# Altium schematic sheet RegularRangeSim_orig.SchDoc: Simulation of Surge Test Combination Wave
size B; SheetNumber: 1; PageSetup: Record=PageOptions¦CenterHorizontal=True¦CenterVertical=True¦PrintScale=0.72¦XCorrection=1.00¦YCorrection=1.00¦PrintKind=0¦BorderSize=5000000¦LeftOffset=0¦BottomOffset=0¦Orientation=2¦PaperLength=1000¦PaperWidth=1000¦Scale=100¦PaperSource=7¦PrintQuality=-4¦MediaType=1¦DitherType=10¦PrintScaleMode=1¦PaperKind=Letter¦PaperIndex=1; nhSheetName: Surge (Combo) Transient; SPICEModelCacheWJGPQAWH: <root> / <DocumentId>WJGPQAWH</DocumentId> / <CacheFrame Number="0"> / <Model Name="v20e275m" Kind="ckt"> / <Text>.subckt V20E275M 1 2 / R1 1 3 100u / B1 3 4 I=1.5e-12*(exp(abs(V(3,4))/22)-1)*sgn(V(3,4)) / C1 3 4 900pF / R2 3 4 4g / L1 4 2 12nH / .ends</Text> / </Model> / <Model Name="vlowr" Kind="mdl"> / <Text>.MODEL VLOWR VSWITCH(RON=1m ROFF=1MEG)</Text> / </Model> / <Model Name="v20e510m" Kind="ckt"> / <Text>.subckt V20E510M 1 2 / R1 1 3 100u / B1 3 4 I=1.0e-5*(exp(abs(V(3,4))/87)-1)*sgn(V(3,4)) / C1 3 4 350pF / R2 3 4 4g / L1 4 2 12nH / .ends</Text> / </Model> / </CacheFrame> / </root>
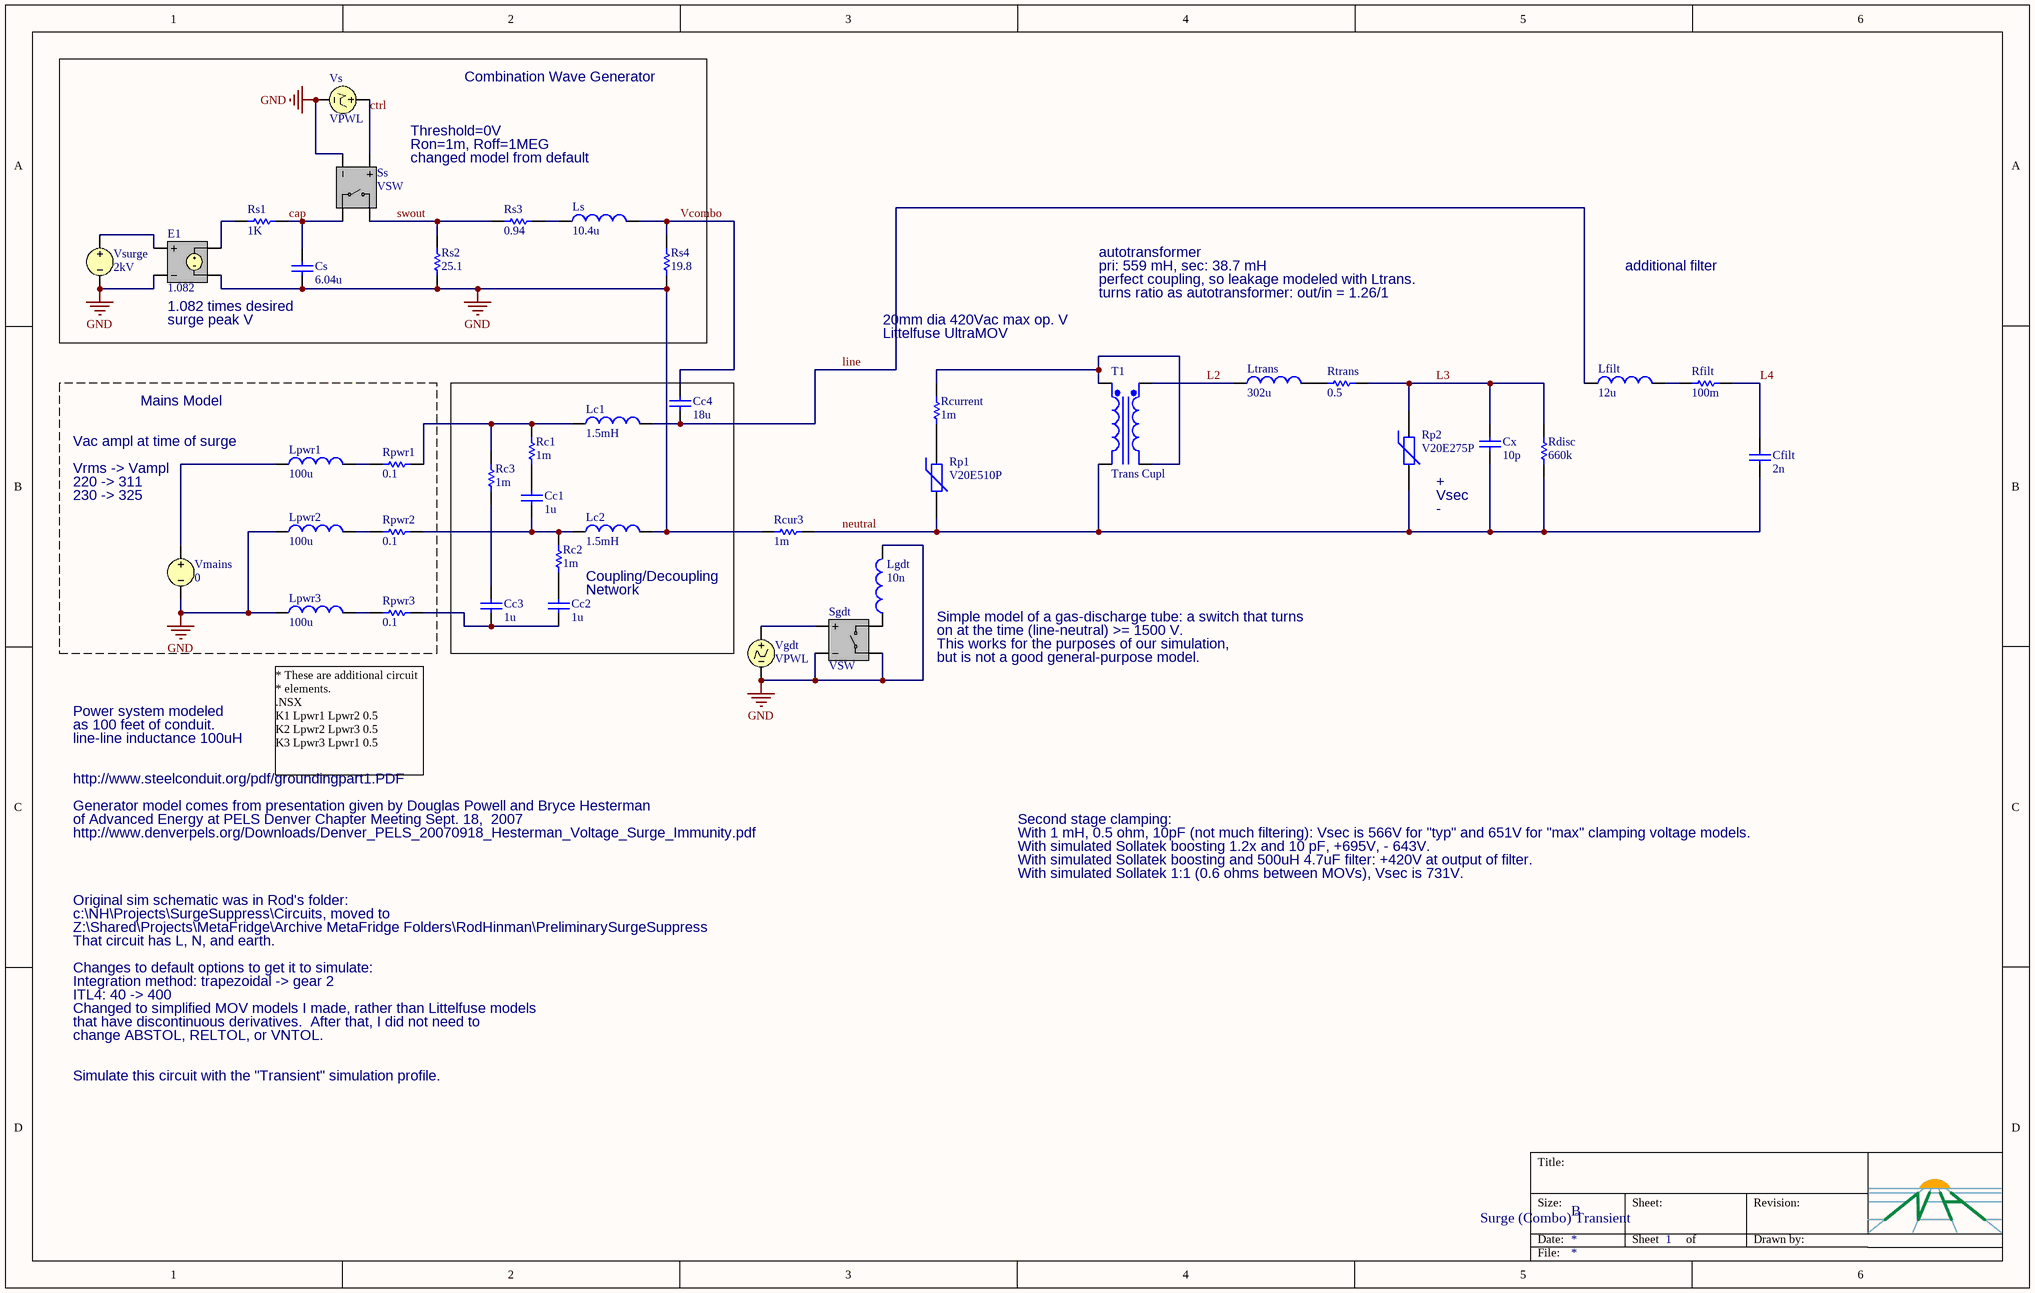
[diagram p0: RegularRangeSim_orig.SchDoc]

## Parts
Cc1  1u  [RAD-0.3]
Cc2  1u  [RAD-0.3]
Cc3  1u  [RAD-0.3]
Cc4  18u  [RAD-0.3]
Cfilt  2n  [RAD-0.3]
Cs  6.04u  [RAD-0.3]
Cx  10p  [RAD-0.3]
E1  1.082
Lc1  1.5mH  [0402-A]
Lc2  1.5mH  [0402-A]
Lfilt  12u  [0402-A]
Lgdt  10n  [0402-A]
Lpwr1  100u  [0402-A]
Lpwr2  100u  [0402-A]
Lpwr3  100u  [0402-A]
Ls  10.4u  [0402-A]
Ltrans  302u  [0402-A]
Rc1  1m  [AXIAL-0.3]
Rc2  1m  [AXIAL-0.3]
Rc3  1m  [AXIAL-0.3]
Rcur3  1m  [AXIAL-0.3]
Rcurrent  1m  [AXIAL-0.3]
Rdisc  660k  [AXIAL-0.3]
Rfilt  100m  [AXIAL-0.3]
Rp1  V20E510P  [6-0805_L]
Rp2  V20E275P  [6-0805_L]
Rpwr1  0.1  [AXIAL-0.3]
Rpwr2  0.1  [AXIAL-0.3]
Rpwr3  0.1  [AXIAL-0.3]
Rs1  1K  [AXIAL-0.3]
Rs2  25.1  [AXIAL-0.3]
Rs3  0.94  [AXIAL-0.3]
Rs4  19.8  [AXIAL-0.3]
Rtrans  0.5  [AXIAL-0.3]
Sgdt  VSW
Ss  VSW
T1  Trans Cupl  [TRF_4]
Vgdt  VPWL
Vmains  0
Vs  VPWL
Vsurge  2kV

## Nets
GND: Cs.2 E1.2(NC-) E1.4(N-) Lc2.2 Lgdt.2 Lpwr2.1 Lpwr3.1 Rcur3.2 Rs2.1 Rs4.1 Sgdt.2(N1-) Sgdt.4(N2-) Ss.2(N1-) Vgdt.2 Vmains.2 Vs.2 Vsurge.2
cap: Cs.1 Rs1.2 Ss.4(N2-)
ctrl: Ss.1(N1+) Vs.1
L2: Ltrans.1 T1.3(Sec+)
L3: Cx.1 Rdisc.2 Rp2.1 Rtrans.2
L4: Cfilt.1 Rfilt.1
line: Cc4.2 Lc1.2 Lfilt.1
neutral: Cfilt.2 Cx.2 Rcur3.1 Rdisc.1 Rp1.2 Rp2.2 T1.2(Pri-)
swout: Rs2.2 Rs3.2 Ss.3(N2+)
Vcombo: Cc4.1 Ls.2 Rs4.2
NetCc1_1: Cc1.1 Rc1.2
NetCc1_2: Cc1.2 Lc2.1 Rc2.1 Rpwr2.2
NetCc2_1: Cc2.1 Rc2.2
NetCc2_2: Cc2.2 Cc3.2 Rpwr3.2
NetCc3_1: Cc3.1 Rc3.2
NetE1_1: E1.1(NC+) Vsurge.1
NetE1_3: E1.3(N+) Rs1.1
NetLc1_1: Lc1.1 Rc1.1 Rc3.1 Rpwr1.2
NetLfilt_2: Lfilt.2 Rfilt.2
NetLgdt_1: Lgdt.1 Sgdt.3(N2+)
NetLpwr1_1: Lpwr1.1 Vmains.1
NetLpwr1_2: Lpwr1.2 Rpwr1.1
NetLpwr2_2: Lpwr2.2 Rpwr2.1
NetLpwr3_2: Lpwr3.2 Rpwr3.1
NetLs_1: Ls.1 Rs3.1
NetLtrans_2: Ltrans.2 Rtrans.1
NetRcurrent_1: Rcurrent.1 T1.1(Pri+) T1.4(Sec-)
NetRcurrent_2: Rcurrent.2 Rp1.1
NetSgdt_1: Sgdt.1(N1+) Vgdt.1

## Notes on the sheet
- Combination Wave Generator
- changed model from default
- Ron=1m, Roff=1MEG
- Threshold=0V
- autotransformer
- pri: 559 mH, sec: 38.7 mH
- perfect coupling, so leakage modeled with Ltrans.
- turns ratio as autotransformer: out/in = 1.26/1
- additional filter
- 1.082 times desired
- surge peak V
- 20mm dia 420Vac max op. V
- Littelfuse UltraMOV
- Mains Model
- Vrms -> Vampl
- 220 -> 311
- (near Lpwr1) Vac ampl at time of surge
- 230 -> 325
- Vsec
- (near Rp2) +
- -
- Coupling/Decoupling
- Network
- Simple model of a gas-discharge tube: a switch that turns
- on at the time (line-neutral) >= 1500 V.
- This works for the purposes of our simulation,
- but is not a good general-purpose model.
- Power system modeled
- as 100 feet of conduit.
- line-line inductance 100uH
- * These are additional circuit
  * elements.
  .NSX
  K1 Lpwr1 Lpwr2 0.5
  K2 Lpwr2 Lpwr3 0.5
  K3 Lpwr3 Lpwr1 0.5
- http://www.steelconduit.org/pdf/groundingpart1.PDF
- Generator model comes from presentation given by Douglas Powell and Bryce Hesterman
- of Advanced Energy at PELS Denver Chapter Meeting Sept. 18,  2007
- http://www.denverpels.org/Downloads/Denver_PELS_20070918_Hesterman_Voltage_Surge_Immunity.pdf
- Second stage clamping:
- With 1 mH, 0.5 ohm, 10pF (not much filtering): Vsec is 566V for "typ" and 651V for "max" clamping voltage models.
- Original sim schematic was in Rod's folder:
- With simulated Sollatek boosting 1.2x and 10 pF, +695V, - 643V.
- With simulated Sollatek boosting and 500uH 4.7uF filter: +420V at output of filter.
- With simulated Sollatek 1:1 (0.6 ohms between MOVs), Vsec is 731V.
- Changes to default options to get it to simulate:
- c:\NH\Projects\SurgeSuppress\Circuits, moved to
- Z:\Shared\Projects\MetaFridge\Archive MetaFridge Folders\RodHinman\PreliminarySurgeSuppress
- That circuit has L, N, and earth.
- Integration method: trapezoidal -> gear 2
- ITL4: 40 -> 400
- Changed to simplified MOV models I made, rather than Littelfuse models
- that have discontinuous derivatives.  After that, I did not need to
- change ABSTOL, RELTOL, or VNTOL.
- Simulate this circuit with the "Transient" simulation profile.

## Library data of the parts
Cc1-Cc4 Cfilt Cs Cx = Cap: Capacitor
E1 = ESRC: Voltage Controlled Voltage Source; Note: PCB Footprint - Not required; Sim Note: Enter gain into gain field
Lc1 Lc2 Lfilt Lgdt Lpwr1-Lpwr3 Ls Ltrans = Inductor: Code_IEC: 1005
Rc1-Rc3 Rcur3 Rcurrent Rdisc Rfilt Rpwr1-Rpwr3 Rs1-Rs4 Rtrans = Res1: Resistor
Rp1 Rp2 = Res Varistor: Varistor (Voltage-Sensitive Resistor)
Sgdt Ss = VSW: Voltage Controlled Switch
T1 = Trans Cupl: Transformer (Coupled Inductor Model)
Vgdt Vs = VPWL: Piecewise Linear Voltage Source; Note: PCB Footprint - Not required; Sim Note: To add model file containing time-current pairs of values, enter model location under "General Tab" in "Full Path" box.
Vmains Vsurge = VSRC: Voltage Source; Note: PCB Footprint - Not required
